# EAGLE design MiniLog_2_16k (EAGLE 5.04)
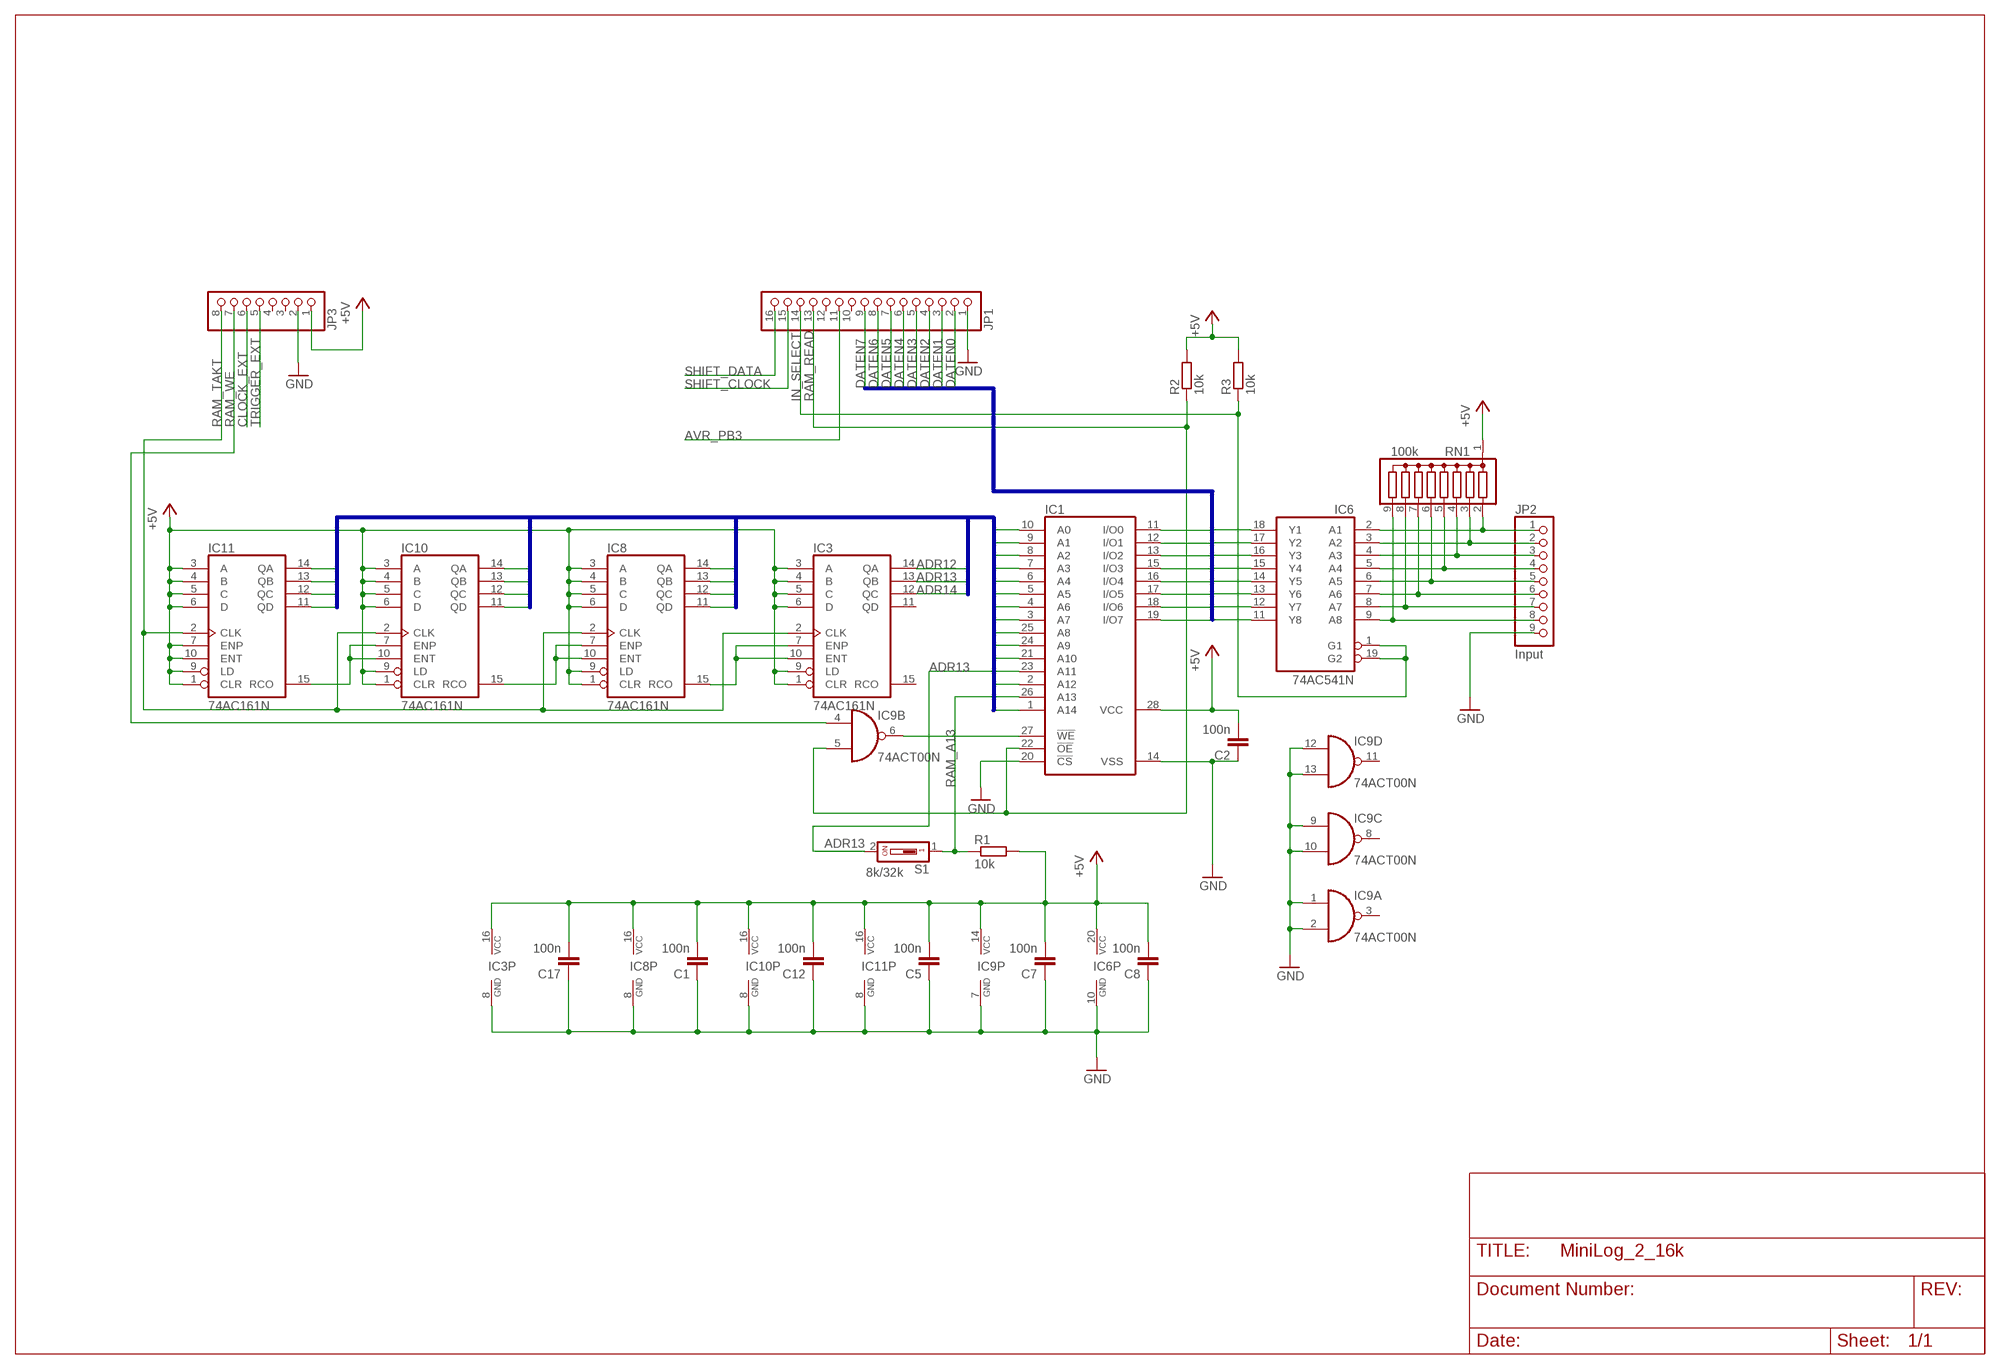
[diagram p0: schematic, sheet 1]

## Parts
C1  100n  C-EU025-025X050  [C025-025X050]
C2  100n  C-EU025-025X050  [C025-025X050]
C5  100n  C-EU025-025X050  [C025-025X050]
C7  100n  C-EU025-025X050  [C025-025X050]
C8  100n  C-EU025-025X050  [C025-025X050]
C12  100n  C-EU025-025X050  [C025-025X050]
C17  100n  C-EU025-025X050  [C025-025X050]
IC1  62832P  [DIL28-3]
IC3  74AC161N  74AC160N  [DIL16]
IC6  74AC541N  [DIL20]
IC8  74AC161N  74AC160N  [DIL16]
IC9  74ACT00N  [DIL14]
IC10  74AC161N  74AC160N  [DIL16]
IC11  74AC161N  74AC160N  [DIL16]
JP1  PINHD-1X16  [1X16]
JP2  Input  PINHD-1X9  [1X09]
JP3  PINHD-1X8  [1X08]
R1  10k  R-EU_0207/10  [0207/10]
R2  10k  R-EU_0207/10  [0207/10]
R3  10k  R-EU_0207/10  [0207/10]
RN1  100k  G08R  [SIL9]
S1  8k/32k  DS01  [DS-01]

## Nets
+5V: C1.2 C2.2 C5.2 C7.2 C8.2 C12.2 C17.2 IC1.28(VCC) IC3.1(CLR) IC3.3(A) IC3.4(B) IC3.5(C) IC3.6(D) IC3.9(LD) IC3.16(VCC) IC6.20(VCC) IC8.1(CLR) IC8.3(A) IC8.4(B) IC8.5(C) IC8.6(D) IC8.9(LD) IC8.16(VCC) IC9.14(P:VCC) IC10.1(CLR) IC10.3(A) IC10.4(B) IC10.5(C) IC10.6(D) IC10.9(LD) IC10.16(VCC) IC11.1(CLR) IC11.3(A) IC11.4(B) IC11.5(C) IC11.6(D) IC11.7(ENP) IC11.9(LD) IC11.10(ENT) IC11.16(VCC) JP3.1 R1.2 R2.2 R3.2 RN1.1
ADR0: IC1.10(A0) IC11.14(QA)
ADR1: IC1.9(A1) IC11.13(QB)
ADR2: IC1.8(A2) IC11.12(QC)
ADR3: IC1.7(A3) IC11.11(QD)
ADR4: IC1.6(A4) IC10.14(QA)
ADR5: IC1.5(A5) IC10.13(QB)
ADR6: IC1.4(A6) IC10.12(QC)
ADR7: IC1.3(A7) IC10.11(QD)
ADR8: IC1.25(A8) IC8.14(QA)
ADR9: IC1.24(A9) IC8.13(QB)
ADR10: IC1.21(A10) IC8.12(QC)
ADR11: IC1.23(A11) IC8.11(QD)
ADR12: IC1.2(A12) IC3.14(QA)
ADR13: IC3.13(QB) S1.2
ADR14: IC1.1(A14) IC3.12(QC)
AVR_PB3: JP1.11
CLOCK_EXT: JP3.6
DATEN0: IC1.11(I/O0) IC6.18(Y1) JP1.2
DATEN1: IC1.12(I/O1) IC6.17(Y2) JP1.3
DATEN2: IC1.13(I/O2) IC6.16(Y3) JP1.4
DATEN3: IC1.15(I/O3) IC6.15(Y4) JP1.5
DATEN4: IC1.16(I/O4) IC6.14(Y5) JP1.6
DATEN5: IC1.17(I/O5) IC6.13(Y6) JP1.7
DATEN6: IC1.18(I/O6) IC6.12(Y7) JP1.8
DATEN7: IC1.19(I/O7) IC6.11(Y8) JP1.9
GND: C1.1 C2.1 C5.1 C7.1 C8.1 C12.1 C17.1 IC1.14(VSS) IC1.20(!CS) IC3.8(GND) IC6.10(GND) IC8.8(GND) IC9.1(A:I0) IC9.2(A:I1) IC9.7(P:GND) IC9.9(C:I0) IC9.10(C:I1) IC9.12(D:I0) IC9.13(D:I1) IC10.8(GND) IC11.8(GND) JP1.1 JP2.9 JP3.2
IN_SELECT: IC6.1(G1) IC6.19(G2) JP1.14 R3.1
N$3: IC6.9(A8) JP2.8 RN1.9
N$4: IC6.8(A7) JP2.7 RN1.8
N$6: IC6.7(A6) JP2.6 RN1.7
N$7: IC6.6(A5) JP2.5 RN1.6
N$8: IC6.5(A4) JP2.4 RN1.5
N$9: IC6.4(A3) JP2.3 RN1.4
N$10: IC6.3(A2) JP2.2 RN1.3
N$11: IC6.2(A1) JP2.1 RN1.2
N$16: IC8.7(ENP) IC8.10(ENT) IC10.15(RCO)
N$17: IC10.7(ENP) IC10.10(ENT) IC11.15(RCO)
N$30: IC1.27(!WE) IC9.6(B:O)
N$52: IC3.7(ENP) IC3.10(ENT) IC8.15(RCO)
RAM_A13: IC1.26(A13) R1.1 S1.1
RAM_READ: IC1.22(!OE) IC9.5(B:I1) JP1.13 R2.1
RAM_TAKT: IC3.2(CLK) IC8.2(CLK) IC10.2(CLK) IC11.2(CLK) JP3.8
RAM_WE: IC9.4(B:I0) JP3.7
SHIFT_CLOCK: JP1.15
SHIFT_DATA: JP1.16
TRIGGER_EXT: JP3.5
Unconnected: IC3.11(QD) IC3.15(RCO) IC9.3(A:O) IC9.8(C:O) IC9.11(D:O) JP1.10 JP1.12 JP3.3 JP3.4

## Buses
ADR[0..14]
DATEN[0..7]

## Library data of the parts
C1 C2 C5 C7 C8 C12 C17 = rcl:C-EU: CAPACITOR, European symbol
IC1 = memory-hitachi:62832P: MEMORY
IC3 IC8 IC10 IC11 = 74xx-eu:74*160: Synchronous 4-bit COUNTER
IC6 = 74xx-eu:74*541: Octal BUFFER and LINE DRIVER, 3-state
IC9 = 74xx-eu:74*00: Quad 2-input NAND gate
JP1 = pinhead:PINHD-1X16: PIN HEADER
JP2 = pinhead:PINHD-1X9: PIN HEADER
JP3 = pinhead:PINHD-1X8: PIN HEADER
R1-R3 = rcl:R-EU_: RESISTOR, European symbol
RN1 = resistor-sil:G08R: SIL RESISTOR
S1 = switch-dil:DS01: DIL/CODE SWITCH

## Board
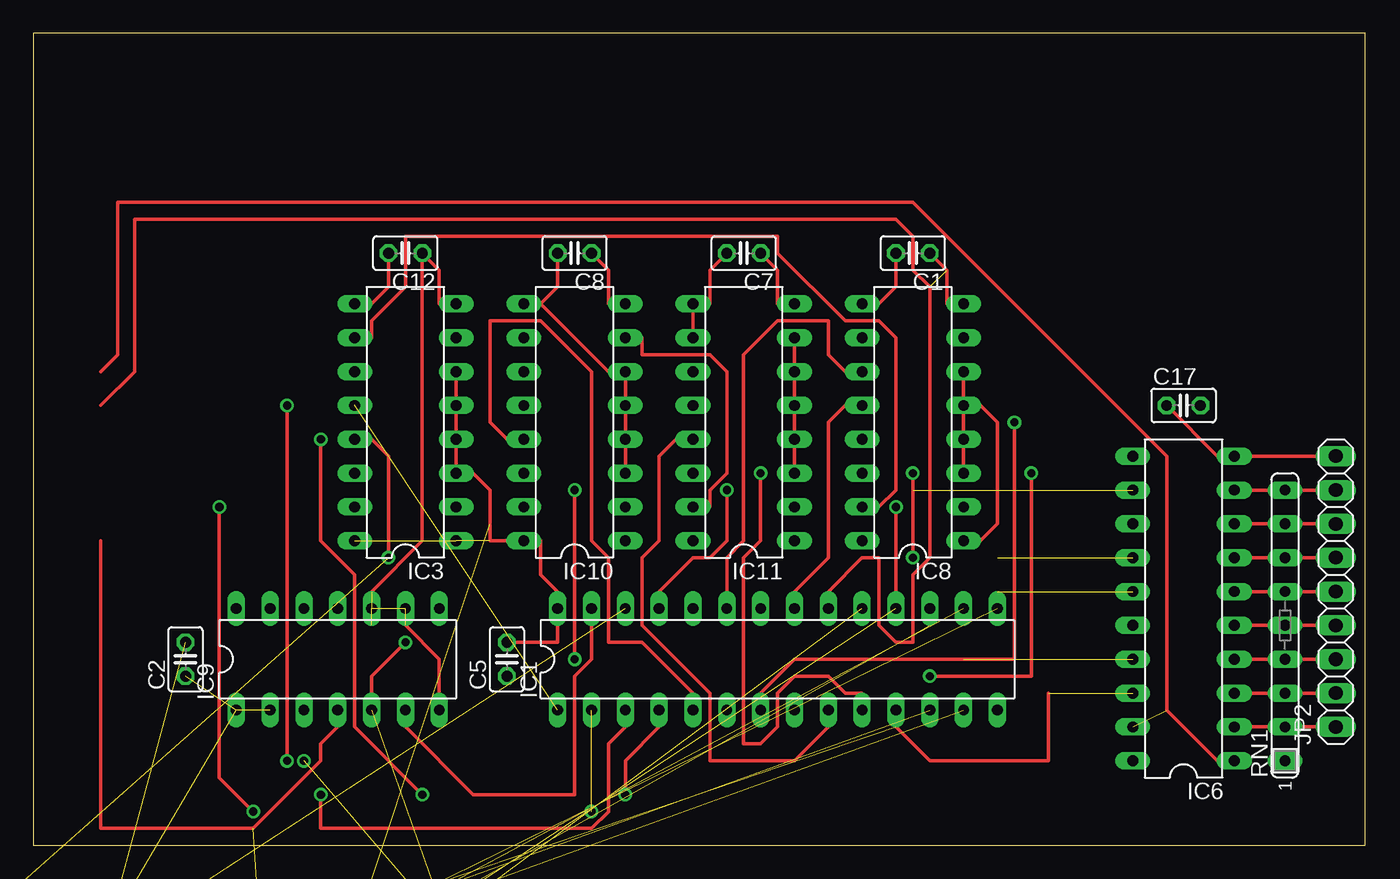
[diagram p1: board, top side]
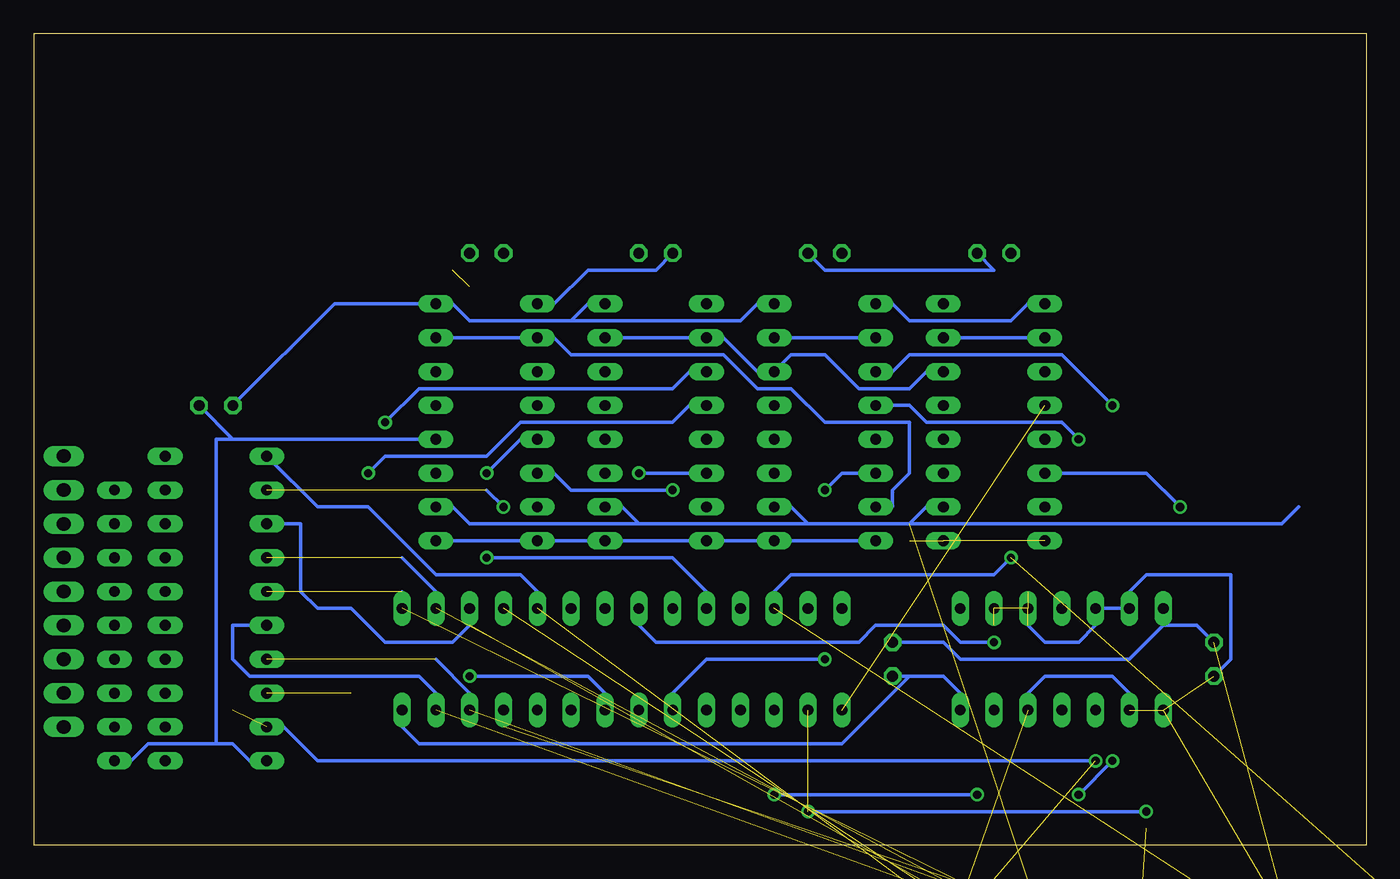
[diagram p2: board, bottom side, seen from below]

Size 100 x 60.95 mm. Coordinates in mm from the lower left corner, seen from the top.
Outline: 0,0 100,0 100,60.95 0,60.95 0,0
Copper layers (1*16): Top 0.035mm / dielectric 1.5mm / Bottom 0.035mm
Design rules "default": minimum track width 10mil, minimum drill 24mil, track to track 8mil, track to pad 8mil, pad to pad 8mil, via to via 8mil, smd to smd 8mil, copper to edge 40mil, drill to drill 8mil, minimum pad ring 10mil, minimum via ring 8mil, stop-mask expansion 4mil, vias tented up to drill 0mil, thermal gap 10mil

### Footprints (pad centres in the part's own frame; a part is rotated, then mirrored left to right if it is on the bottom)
C025-025X050 = drill 0.813 octagon: 1 -1.27,0; 2 1.27,0
DIL28-3 = drill 0.813 long: 1 -16.51,-3.81; 2 -13.97,-3.81; 3 -11.43,-3.81; 4 -8.89,-3.81; 5 -6.35,-3.81; 6 -3.81,-3.81; 7 -1.27,-3.81; 8 1.27,-3.81; 9 3.81,-3.81; 10 6.35,-3.81; 11 8.89,-3.81; 12 11.43,-3.81; 13 13.97,-3.81; 14 16.51,-3.81; 15 16.51,3.81; 16 13.97,3.81; 17 11.43,3.81; 18 8.89,3.81; 19 6.35,3.81; 20 3.81,3.81; 21 1.27,3.81; 22 -1.27,3.81; 23 -3.81,3.81; 24 -6.35,3.81; 25 -8.89,3.81; 26 -11.43,3.81; 27 -13.97,3.81; 28 -16.51,3.81
DIL16 = drill 0.813 long: 1 -8.89,-3.81; 2 -6.35,-3.81; 3 -3.81,-3.81; 4 -1.27,-3.81; 5 1.27,-3.81; 6 3.81,-3.81; 7 6.35,-3.81; 8 8.89,-3.81; 9 8.89,3.81; 10 6.35,3.81; 11 3.81,3.81; 12 1.27,3.81; 13 -1.27,3.81; 14 -3.81,3.81; 15 -6.35,3.81; 16 -8.89,3.81
DIL20 = drill 0.813 long: 1 -11.43,-3.81; 2 -8.89,-3.81; 3 -6.35,-3.81; 4 -3.81,-3.81; 5 -1.27,-3.81; 6 1.27,-3.81; 7 3.81,-3.81; 8 6.35,-3.81; 9 8.89,-3.81; 10 11.43,-3.81; 11 11.43,3.81; 12 8.89,3.81; 13 6.35,3.81; 14 3.81,3.81; 15 1.27,3.81; 16 -1.27,3.81; 17 -3.81,3.81; 18 -6.35,3.81; 19 -8.89,3.81; 20 -11.43,3.81
DIL14 = drill 0.813 long: 1 -7.62,-3.81; 2 -5.08,-3.81; 3 -2.54,-3.81; 4 0,-3.81; 5 2.54,-3.81; 6 5.08,-3.81; 7 7.62,-3.81; 8 7.62,3.81; 9 5.08,3.81; 10 2.54,3.81; 11 0,3.81; 12 -2.54,3.81; 13 -5.08,3.81; 14 -7.62,3.81
1X16 = drill 1.016 long: 1 -19.05,0; 2 -16.51,0; 3 -13.97,0; 4 -11.43,0; 5 -8.89,0; 6 -6.35,0; 7 -3.81,0; 8 -1.27,0; 9 1.27,0; 10 3.81,0; 11 6.35,0; 12 8.89,0; 13 11.43,0; 14 13.97,0; 15 16.51,0; 16 19.05,0
1X09 = drill 1.016 long: 1 -10.16,0; 2 -7.62,0; 3 -5.08,0; 4 -2.54,0; 5 0,0; 6 2.54,0; 7 5.08,0; 8 7.62,0; 9 10.16,0
1X08 = drill 1.016 long: 1 -8.89,0; 2 -6.35,0; 3 -3.81,0; 4 -1.27,0; 5 1.27,0; 6 3.81,0; 7 6.35,0; 8 8.89,0
0207/10 = drill 0.813 octagon: 1 -5.08,0; 2 5.08,0
SIL9 = drill 0.813 long: 1 -10.16,0; 2 -7.62,0; 3 -5.08,0; 4 -2.54,0; 5 0,0; 6 2.54,0; 7 5.08,0; 8 7.62,0; 9 10.16,0
DS-01 = drill 0.813 long: 1 0,-3.81; 2 0,3.81

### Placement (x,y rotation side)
C1  66.04,44.45 180 top
C2  11.43,13.97 90 top
C5  35.56,13.97 90 top
C7  53.34,44.45 180 top
C8  40.64,44.45 180 top
C12  27.94,44.45 180 top
C17  86.36,33.02 0 top
IC1  55.88,13.97 0 top
IC3  27.94,31.75 90 top
IC6  86.36,17.78 90 top
IC8  66.04,31.75 90 top
IC9  22.86,13.97 0 top
IC10  40.64,31.75 90 top
IC11  53.34,31.75 90 top
JP1  not placed on the board
JP2  97.79,19.05 90 top
JP3  not placed on the board
R1  not placed on the board
R2  not placed on the board
R3  not placed on the board
RN1  93.98,16.51 90 top
S1  not placed on the board

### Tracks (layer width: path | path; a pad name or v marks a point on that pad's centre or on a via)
+5V  (6 unrouted)
  Top 0.254: C12.2 26.67,41.91 25.4,40.64 IC3.9 | 38.1,40.64 39.37,41.91 C8.2 | IC10.3 IC10.4 IC10.5 IC10.6 43.18,35.56 38.1,40.64 | 38.1,40.64 IC10.9 | IC11.3 IC11.4 IC11.5 IC11.6 IC11.7 | C1.2 64.77,41.91 63.5,40.64 IC8.9 | IC11.10 IC11.9 50.8,40.64 50.8,43.18 C7.2 | IC8.5 IC8.6 | IC8.3 IC8.4 IC8.5 | C5.2 39.37,15.24 IC1.28 39.37,19.05 38.1,20.32 38.1,22.86 IC10.16 34.29,22.86 34.29,26.67 33.02,27.94 IC3.3 IC3.4 IC3.5 IC3.6 | IC8.5 71.12,33.02 72.39,31.75 72.39,24.13 71.12,22.86 IC8.1
  Bottom 0.254: C7.2 53.34,43.18 58.42,43.18 60.96,40.64 IC8.9 | IC11.7 IC11.10 48.26,38.1 45.72,35.56 IC10.6 43.18,36.83 40.64,36.83 38.1,34.29 34.29,34.29 33.02,35.56 IC3.6 | IC3.9 25.4,40.64 26.67,39.37 34.29,39.37 35.56,40.64 IC10.9 | 86.36,7.62 91.44,7.62 92.71,6.35 RN1.1 | 86.36,7.62 85.09,7.62 83.82,6.35 IC6.20 | 85.09,30.48 C17.2 | IC8.4 85.09,30.48 | 86.36,7.62 86.36,30.48 85.09,30.48 | C2.2 12.7,16.51 15.24,16.51 | 15.24,16.51 17.78,13.97 30.48,13.97 31.75,15.24 C5.2 | 15.24,16.51 IC9.14 | IC8.1 IC8.16 IC11.1 IC11.16 IC10.1 IC10.16
ADR0  (via drill 0.61)
  Top 0.254: v54.61,27.94 54.61,22.86 53.34,21.59 53.34,7.62 54.61,7.62 55.88,8.89 55.88,11.43 57.15,12.7 59.69,12.7 60.96,11.43 62.23,11.43 IC1.10
  Bottom 0.254: v54.61,27.94 IC11.14
ADR1
  Top 0.254: IC1.9 59.69,8.89 57.15,6.35 50.8,6.35 50.8,11.43 45.72,16.51 45.72,21.59 46.99,22.86 46.99,29.21 48.26,30.48 IC11.13
ADR2  (via drill 0.61)
  Top 0.254: v67.31,12.7 74.93,12.7 v74.93,27.94
  Bottom 0.254: v67.31,12.7 58.42,12.7 57.15,11.43 IC1.8 | v74.93,27.94 73.66,29.21 66.04,29.21 63.5,31.75 52.07,31.75 50.8,33.02 IC11.12
ADR3  (via drill 0.61)
  Top 0.254: v73.66,31.75 73.66,13.97 57.15,13.97 54.61,11.43 IC1.7
  Bottom 0.254: v73.66,31.75 71.12,34.29 52.07,34.29 50.8,35.56 IC11.11
ADR4  (via drill 0.61)
  Top 0.254: v40.64,13.97 v40.64,26.67
  Bottom 0.254: v40.64,13.97 49.53,13.97 52.07,11.43 IC1.6 | v40.64,26.67 39.37,27.94 IC10.14
ADR5
  Top 0.254: IC1.5 49.53,11.43 45.72,15.24 43.18,15.24 43.18,21.59 41.91,22.86 41.91,35.56 38.1,39.37 34.29,39.37 34.29,31.75 35.56,30.48 IC10.13
ADR6  (via drill 0.61)
  Top 0.254: v44.45,3.81 44.45,6.35 46.99,8.89 IC1.4 | v29.21,3.81 24.13,8.89 24.13,20.32 21.59,22.86 v21.59,30.48
  Bottom 0.254: v29.21,3.81 v44.45,3.81 | v21.59,30.48 22.86,31.75 33.02,31.75 34.29,33.02 IC10.12
ADR7  (via drill 0.61)
  Top 0.254: v21.59,3.81 21.59,1.27 41.91,1.27 43.18,2.54 43.18,7.62 44.45,8.89 IC1.3 | v19.05,6.35 v19.05,33.02
  Bottom 0.254: v21.59,3.81 v19.05,6.35 | v19.05,33.02 22.86,36.83 34.29,36.83 35.56,35.56 IC10.11
ADR8  (via drill 0.61)
  Top 0.254: v52.07,26.67 52.07,22.86 50.8,21.59 49.53,21.59 46.99,19.05 IC1.25
  Bottom 0.254: v52.07,26.67 59.69,26.67 60.96,27.94 IC8.14
ADR9  (via drill 0.61)
  Top 0.254: v66.04,21.59 v66.04,27.94
  Bottom 0.254: v66.04,21.59 52.07,21.59 49.53,19.05 IC1.24 | v66.04,27.94 63.5,30.48 IC8.13
ADR10
  Top 0.254: IC1.21 57.15,19.05 59.69,21.59 59.69,31.75 60.96,33.02 IC8.12
ADR11
  Top 0.254: IC1.23 52.07,21.59 53.34,22.86 53.34,36.83 55.88,39.37 59.69,39.37 59.69,36.83 60.96,35.56 IC8.11
ADR12  (via drill 0.61)  (1 unrouted)
  Top 0.254: v16.51,2.54 13.97,5.08 v13.97,25.4
  Bottom 0.254: v16.51,2.54 v41.91,2.54 | v13.97,25.4 16.51,27.94 IC3.14
ADR13  (via drill 0.61)  (1 unrouted)
  Top 0.254: v26.67,21.59 26.67,29.21 25.4,30.48 IC3.13
  Bottom 0.254: v26.67,21.59 27.94,20.32 43.18,20.32 44.45,19.05
ADR14  (1 unrouted)
DATEN0  (2 unrouted)
  Top 0.254: 76.2,11.43 76.2,6.35 67.31,6.35 64.77,8.89 IC1.11
DATEN1  (2 unrouted)
  Bottom 0.254: 69.85,13.97 67.31,11.43 IC1.12
DATEN2  (1 unrouted)
  Bottom 0.254: IC1.13 69.85,11.43 71.12,12.7 83.82,12.7 85.09,13.97 85.09,16.51 IC6.16
DATEN3  (2 unrouted)
  Bottom 0.254: IC1.15 72.39,19.05
DATEN4  (2 unrouted)
  Bottom 0.254: 72.39,21.59 69.85,19.05 IC1.16
DATEN5  (1 unrouted)
  Bottom 0.254: IC1.17 67.31,16.51 68.58,15.24 73.66,15.24 76.2,17.78 78.74,17.78 80.01,19.05 80.01,24.13 IC6.13
DATEN6  (via drill 0.61)  (2 unrouted)
  Top 0.254: IC1.18 v64.77,25.4
  Bottom 0.254: v64.77,25.4 66.04,26.67
DATEN7  (1 unrouted)
  Bottom 0.254: IC6.11 78.74,25.4 74.93,25.4 69.85,20.32 63.5,20.32 62.23,19.05 IC1.19
GND  (9 unrouted)
  Top 0.254: 27.94,16.51 30.48,13.97 IC9.7 | C8.1 43.18,43.18 43.18,40.64 IC10.8 | IC3.8 30.48,40.64 30.48,43.18 C12.1 29.21,22.86 25.4,19.05 | JP2.9 IC6.10 88.9,29.21 C17.1 | C7.1 55.88,43.18 55.88,40.64 IC11.8 | C1.1 68.58,43.18 68.58,40.64 IC8.8 | 5.08,33.02 7.62,35.56 7.62,46.99 64.77,46.99 66.04,45.72 66.04,43.18 67.31,41.91 67.31,21.59 66.04,20.32 66.04,15.24 64.77,15.24 63.5,16.51 63.5,21.59 62.23,21.59 59.69,19.05 IC1.20
  Bottom 0.254: C2.1 10.16,13.97 10.16,20.32 16.51,20.32 17.78,19.05 IC9.13 IC9.12 20.32,16.51 21.59,15.24 24.13,15.24 25.4,16.51 | 34.29,12.7 C5.1 | 34.29,12.7 31.75,12.7 30.48,11.43 IC9.7 | 34.29,12.7 39.37,7.62 71.12,7.62 72.39,8.89 IC1.14 | C12.1 27.94,43.18 40.64,43.18 C8.1 | 59.69,39.37 58.42,40.64 IC11.8 | 59.69,39.37 67.31,39.37 68.58,40.64 IC8.8 77.47,40.64 C17.1 | 59.69,39.37 46.99,39.37 45.72,40.64 IC10.8
IN_SELECT  (via drill 0.61)  (3 unrouted)
  Top 0.254: 5.08,35.56 6.35,36.83 6.35,48.26 66.04,48.26 85.09,29.21 85.09,10.16 88.9,6.35 IC6.1
  Bottom 0.254: v20.32,6.35 78.74,6.35 81.28,8.89 IC6.19
N$3
  Top 0.254: IC6.9 RN1.9 JP2.8
N$4
  Top 0.254: IC6.8 RN1.8 JP2.7
N$6
  Top 0.254: IC6.7 RN1.7 JP2.6
N$7
  Top 0.254: IC6.6 RN1.6 JP2.5
N$8
  Top 0.254: IC6.5 RN1.5 JP2.4
N$9
  Top 0.254: IC6.4 RN1.4 JP2.3
N$10
  Top 0.254: IC6.3 RN1.3 JP2.2
N$11
  Top 0.254: IC6.2 RN1.2 JP2.1
N$16
  Bottom 0.254: IC10.15 35.56,25.4 35.56,26.67 34.29,27.94 34.29,31.75 40.64,31.75 43.18,34.29 45.72,34.29 48.26,36.83 59.69,36.83 60.96,38.1 IC8.10 IC8.7
N$17
  Top 0.254: IC11.15 50.8,25.4 50.8,26.67 52.07,27.94 52.07,35.56 50.8,36.83 45.72,36.83 45.72,38.1 IC10.7
  Bottom 0.254: IC10.7 IC10.10
N$30
  Top 0.254: IC9.6 27.94,8.89 33.02,3.81 40.64,3.81 40.64,12.7 41.91,13.97 IC1.27
N$52
  Top 0.254: IC8.15 63.5,25.4 64.77,26.67 64.77,38.1 63.5,39.37 60.96,39.37 55.88,44.45 55.88,45.72 27.94,45.72 27.94,41.91 25.4,39.37 25.4,38.1 IC3.10
  Bottom 0.254: IC3.10 IC3.7
RAM_A13  (2 unrouted)
RAM_READ  (via drill 0.61)  (2 unrouted)
  Top 0.254: v27.94,15.24 25.4,12.7 IC9.5
  Bottom 0.254: 17.78,11.43 19.05,12.7 24.13,12.7 25.4,11.43 IC9.5 | v27.94,15.24 30.48,15.24 31.75,16.51 36.83,16.51 38.1,15.24 53.34,15.24 54.61,16.51 IC1.22
RAM_TAKT  (1 unrouted)
  Bottom 0.254: 34.29,24.13 33.02,25.4 IC3.2 | 34.29,24.13 41.91,24.13 | 41.91,24.13 43.18,25.4 IC10.2 | 54.61,24.13 55.88,25.4 IC11.2 | 41.91,24.13 54.61,24.13 | 54.61,24.13 67.31,24.13 68.58,25.4 IC8.2 | 5.08,25.4 6.35,24.13 34.29,24.13
RAM_WE  (1 unrouted)
  Top 0.254: 5.08,22.86 5.08,1.27 16.51,1.27 21.59,6.35 21.59,7.62 22.86,8.89 IC9.4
